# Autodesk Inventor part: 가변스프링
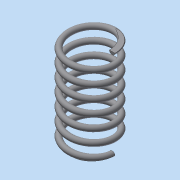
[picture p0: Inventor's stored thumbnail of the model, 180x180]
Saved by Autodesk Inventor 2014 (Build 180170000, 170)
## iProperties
Created: 2022-08
Part Number: 가변스프링
Material: 일반
Document SubType Name: Modeling
Designer: dg
Density: 1 g/cm^3
Appearance: 기본값
Mass: 8.73452 g
Surface Area: 88.4296 cm^2
Volume: 8.73452 cm^3
Author: dg
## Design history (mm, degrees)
sketch "스케치1"
  geometry: L1 (0, 0)-(0, 64); L2 (0, 0)-(16, 0); L3 (0, 64)-(16, 64); C1 r 2 at (16, 0)
  constraints: 6 end point, 1 centre point, 1 coincident, 1 parallel, 1 perpendicular, 1 vertical, 1 vertical alignment
  dimensions: "d0" = 64 distance of L1.start L1.end (derived); "d1" = 32 diameter of L2.end L1; "d2" = 4 diameter of C1
feature "코일1" pitch "d3" = 10; turns "d5" = 7; dims "d4" = 64 (= d0), "d6" = 0, angle "d7" = 90 deg, angle "d8" = 90 deg, "d9" = 0, "d10" = 0
node "작업 평면1"
node "작업 평면2"
feature "분할1"
feature "분할2"
node "솔리드1"
other parameters: "d11" = 0, "d12" = 0
